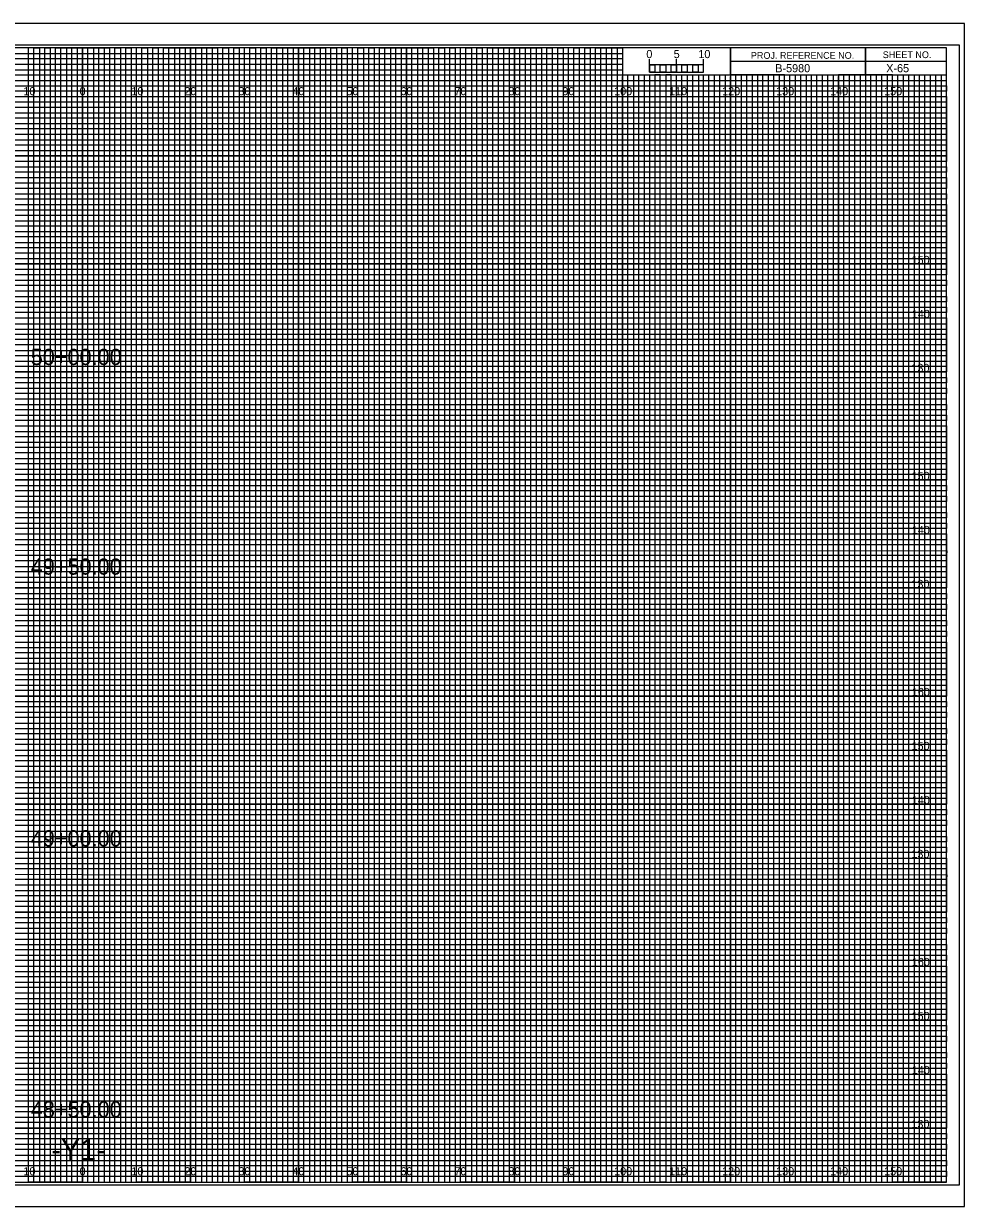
# Model space of a CAD drawing. Extents: x -13 to 323, y -5 to 4834.
# Drawn here: x 149.1 to 323.3, y 4175.5 to 4394.5 of the extents above; entities that cross this region are included whole.
import ezdxf

# ---------------------------------------------------------------- set-up
doc = ezdxf.new("R2010")
doc.units = 0
for name, color, linetype in [('Exist CMT Pavement', 7, 'Continuous'), ('Exist Cross Section Cell', 7, 'Continuous'), ('Exist XS Center Line Elevation Label', 7, 'Continuous'), ('Exist XS Ground Line', 7, 'Continuous'), ('Prop CMT Pvmt Course 1', 7, 'Continuous'), ('Prop CMT Pvmt Course 1 Wedge', 7, 'Continuous'), ('Prop CMT Pvmt Course 2', 7, 'Continuous'), ('Prop CMT Pvmt Course 2 Wedge', 7, 'Continuous'), ('Prop CMT Pvmt Course 3', 7, 'Continuous'), ('Prop CMT Pvmt Course 3 Wedge', 7, 'Continuous'), ('Prop CMT Pvmt Surface', 7, 'Continuous'), ('Prop CMT Pvmt Surface Shoulder', 7, 'Continuous'), ('Prop CMT Shld Paved Course 1', 7, 'Continuous'), ('Prop CMT Shld Paved Course 2', 7, 'Continuous'), ('Prop CMT Shld Paved Course 3', 7, 'Continuous'), ('Prop CMT Slope Grass', 7, 'Continuous'), ('Prop CMT Subgrade Earthwork', 7, 'Continuous')]:
    doc.layers.add(name, color=color, linetype=linetype)

msp = doc.modelspace()

# ---------------------------------------------------------------- linework, layer by layer
at = {"layer": 'Exist XS Center Line Elevation Label'}
for points in [[(145, 4180), (155, 4180), (155, 4390), (165, 4390), (165, 4180), (175, 4180), (175, 4390), (185, 4390), (185, 4180), (195, 4180), (195, 4390), (205, 4390), (205, 4180), (215, 4180), (215, 4390), (225, 4390), (225, 4180), (235, 4180), (235, 4390), (245, 4390), (245, 4180), (255, 4180), (255, 4390), (259.93, 4390), (260, 4390), (260, 4385), (264.99, 4385), (264.99, 4180), (275, 4180), (275, 4385), (285, 4385), (285, 4180), (295, 4180), (295, 4385), (305, 4385), (305, 4180), (315, 4180), (315, 4385)], [(0, 4385), (275, 4385)], [(0, 4365), (320, 4365), (320, 4375), (0, 4375)], [(0, 4345), (320, 4345), (320, 4355), (0, 4355)], [(0, 4325), (320, 4325), (320, 4335), (0, 4335)], [(0, 4305), (320, 4305), (320, 4315), (0, 4315)], [(0, 4285), (320, 4285), (320, 4295), (0, 4295)], [(0, 4265), (320, 4265), (320, 4275), (0, 4275)], [(0, 4245), (320, 4245), (320, 4255), (0, 4255)], [(0, 4225), (320, 4225), (320, 4235), (0, 4235)], [(0, 4205), (320, 4205), (320, 4215), (0, 4215)], [(0, 4185), (320, 4185), (320, 4195), (0, 4195)]]:
    msp.add_lwpolyline(points, dxfattribs=at)
at = {"layer": 'Exist XS Ground Line'}
for p, q in [((150, 4390), (140, 4390)), ((150, 4180), (150, 4390)), ((170, 4390), (160, 4390)), ((160, 4390), (160, 4180)), ((170, 4180), (170, 4390)), ((190, 4390), (180, 4390)), ((180, 4390), (180, 4180)), ((190, 4180), (190, 4390)), ((210, 4390), (200, 4390)), ((200, 4390), (200, 4180)), ((210, 4180), (210, 4390)), ((230, 4390), (220, 4390)), ((220, 4390), (220, 4180)), ((230, 4180), (230, 4390)), ((250, 4390), (240, 4390)), ((240, 4390), (240, 4180)), ((250, 4180), (250, 4390)), ((260, 4390), (260, 4180)), ((270, 4180), (270, 4385)), ((290, 4385), (280, 4385)), ((280, 4385), (280, 4180)), ((290, 4180), (290, 4385)), ((310, 4385), (300, 4385)), ((300, 4385), (300, 4180)), ((310, 4180), (310, 4385)), ((160, 4180), (150, 4180)), ((180, 4180), (170, 4180)), ((200, 4180), (190, 4180)), ((220, 4180), (210, 4180)), ((240, 4180), (230, 4180)), ((260, 4180), (250, 4180)), ((280, 4180), (270, 4180)), ((300, 4180), (290, 4180)), ((320, 4180), (310, 4180)), ((320, 4180), (320, 4180))]:
    msp.add_line(p, q, dxfattribs=at)
for points in [[(0, 4380), (320, 4380), (320, 4370), (0, 4370)], [(0, 4360), (320, 4360), (320, 4350), (0, 4350)], [(0, 4340), (320, 4340), (320, 4330), (0, 4330)], [(0, 4320), (320, 4320), (320, 4310), (0, 4310)], [(0, 4300), (320, 4300), (320, 4290), (0, 4290)], [(0, 4280), (320, 4280), (320, 4270), (0, 4270)], [(0, 4260), (320, 4260), (320, 4250), (0, 4250)], [(0, 4240), (320, 4240), (320, 4230), (0, 4230)], [(0, 4220), (320, 4220), (320, 4210), (0, 4210)], [(0, 4200), (320, 4200), (320, 4190), (0, 4190)]]:
    msp.add_lwpolyline(points, dxfattribs=at)
at = {"layer": 'Prop CMT Pvmt Course 1'}
for p, q in [((267, 4385), (266.01, 4385)), ((266.01, 4385), (266.01, 4180)), ((267, 4180), (267, 4385)), ((269, 4385), (268, 4385)), ((268, 4385), (268, 4180)), ((269, 4180), (269, 4385)), ((266.01, 4180), (265, 4180)), ((268, 4180), (267, 4180))]:
    msp.add_line(p, q, dxfattribs=at)
for points in [[(150, 4180), (151, 4180), (151, 4390), (152, 4390), (152, 4180)], [(152, 4180), (153, 4180), (153, 4390), (154, 4390), (154, 4180)], [(155, 4180), (156, 4180), (156, 4390), (157, 4390), (157, 4180)], [(157, 4180), (158, 4180), (158, 4390), (159, 4390), (159, 4180)], [(160, 4180), (161, 4180), (161, 4390), (162, 4390), (162, 4180)], [(162, 4180), (163, 4180), (163, 4390), (164, 4390), (164, 4180)], [(165, 4180), (166, 4180), (166, 4390), (167, 4390), (167, 4180)], [(167, 4180), (168, 4180), (168, 4390), (169, 4390), (169, 4180)], [(170, 4180), (171, 4180), (171, 4390), (172, 4390), (172, 4180)], [(172, 4180), (173, 4180), (173, 4390), (174, 4390), (174, 4180)], [(175, 4180), (176, 4180), (176, 4390), (177, 4390), (177, 4180)], [(177, 4180), (178, 4180), (178, 4390), (179, 4390), (179, 4180)], [(180, 4180), (181, 4180), (181, 4390), (182, 4390), (182, 4180)], [(182, 4180), (183, 4180), (183, 4390), (184, 4390), (184, 4180)], [(185, 4180), (186, 4180), (186, 4390), (187, 4390), (187, 4180)], [(187, 4180), (188, 4180), (188, 4390), (189, 4390), (189, 4180)], [(190, 4180), (191, 4180), (191, 4390), (192, 4390), (192, 4180)], [(192, 4180), (193, 4180), (193, 4390), (194, 4390), (194, 4180)], [(195, 4180), (196, 4180), (196, 4390), (197, 4390), (197, 4180)], [(197, 4180), (198, 4180), (198, 4390), (199, 4390), (199, 4180)], [(200, 4180), (201, 4180), (201, 4390), (202, 4390), (202, 4180)], [(202, 4180), (203, 4180), (203, 4390), (204, 4390), (204, 4180)], [(205, 4180), (206, 4180), (206, 4390), (207, 4390), (207, 4180)], [(207, 4180), (208, 4180), (208, 4390), (209, 4390), (209, 4180)], [(210, 4180), (211, 4180), (211, 4390), (212, 4390), (212, 4180)], [(212, 4180), (213, 4180), (213, 4390), (214, 4390), (214, 4180)], [(215, 4180), (216, 4180), (216, 4390), (217, 4390), (217, 4180)], [(217, 4180), (218, 4180), (218, 4390), (219, 4390), (219, 4180)], [(220, 4180), (221, 4180), (221, 4390), (222, 4390), (222, 4180)], [(222, 4180), (223, 4180), (223, 4390), (224, 4390), (224, 4180)], [(225, 4180), (226, 4180), (226, 4390), (227, 4390), (227, 4180)], [(227, 4180), (228, 4180), (228, 4390), (229, 4390), (229, 4180)], [(230, 4180), (231, 4180), (231, 4390), (232, 4390), (232, 4180)], [(232, 4180), (233, 4180), (233, 4390), (234, 4390), (234, 4180)], [(235, 4180), (236, 4180), (236, 4390), (237, 4390), (237, 4180)], [(237, 4180), (238, 4180), (238, 4390), (239, 4390), (239, 4180)], [(240, 4180), (241, 4180), (241, 4390), (242, 4390), (242, 4180)], [(242, 4180), (243, 4180), (243, 4390), (244, 4390), (244, 4180)], [(245, 4180), (246, 4180), (246, 4390), (247, 4390), (247, 4180)], [(247, 4180), (248, 4180), (248, 4390), (249, 4390), (249, 4180)], [(250, 4180), (251, 4180), (251, 4390), (252, 4390), (252, 4180)], [(252, 4180), (253, 4180), (253, 4390), (254, 4390), (254, 4180)], [(255, 4180), (256, 4180), (256, 4390), (257, 4390), (257, 4180)], [(257, 4180), (258, 4180), (258, 4390), (259, 4390), (259, 4180)], [(260, 4180), (261, 4180), (261, 4385), (262.02, 4385), (262.02, 4180)], [(262, 4180), (263, 4180), (263, 4385), (263.99, 4385), (263.99, 4180)], [(270, 4180), (270.98, 4180), (270.98, 4385), (272, 4385), (272, 4180)], [(272, 4180), (273, 4180), (273, 4385), (274.05, 4385), (274.05, 4180)], [(275, 4180), (276, 4180), (276, 4385), (277, 4385), (277, 4180)], [(277, 4180), (278, 4180), (278, 4385), (279, 4385), (279, 4180)], [(280, 4180), (281, 4180), (281, 4385), (282, 4385), (282, 4180)], [(282, 4180), (283, 4180), (283, 4385), (284, 4385), (284, 4180)], [(285, 4180), (286, 4180), (286, 4385), (287, 4385), (287, 4180)], [(287, 4180), (288, 4180), (288, 4385), (289, 4385), (289, 4180)], [(290, 4180), (291, 4180), (291, 4385), (292, 4385), (292, 4180)], [(292, 4180), (293, 4180), (293, 4385), (294, 4385), (294, 4180)], [(295, 4180), (296, 4180), (296, 4385), (297, 4385), (297, 4180)], [(297, 4180), (298, 4180), (298, 4385), (299, 4385), (299, 4180)], [(300, 4180), (301, 4180), (301, 4385), (302, 4385), (302, 4180)], [(302, 4180), (303, 4180), (303, 4385), (304, 4385), (304, 4180)], [(305, 4180), (306, 4180), (306, 4385), (307, 4385), (307, 4180)], [(307, 4180), (308, 4180), (308, 4385), (309, 4385), (309, 4180)], [(310, 4180), (311, 4180), (311, 4385), (312, 4385), (312, 4180)], [(312, 4180), (313, 4180), (313, 4385), (314, 4385), (314, 4180)], [(315, 4180), (316, 4180), (316, 4385), (317, 4385), (317, 4180)], [(317, 4180), (318, 4180), (318, 4385), (319, 4385), (319, 4180)]]:
    msp.add_lwpolyline(points, dxfattribs=at)
at = {"layer": 'Prop CMT Pvmt Course 2'}
for p, q in [((323.3, 4394.5), (-13.4, 4394.5)), ((-13.4, 4175.5), (323.3, 4175.5))]:
    msp.add_line(p, q, dxfattribs=at)
at = {"layer": 'Prop CMT Pvmt Surface Shoulder'}
for p, q in [((305, 4390), (305, 4385)), ((305, 4385), (305, 4390)), ((280, 4387.5), (280, 4385)), ((320, 4387.49), (280, 4387.49)), ((280, 4385), (320, 4385))]:
    msp.add_line(p, q, dxfattribs=at)
for points in [[(320, 4390), (0, 4390), (0, 4180), (320, 4180)], [(280, 4390), (260, 4390), (260, 4385.03), (280, 4385.03)], [(320, 4390), (280, 4390), (280, 4385), (320, 4385)]]:
    msp.add_lwpolyline(points, close=True, dxfattribs=at)
at = {"layer": 'Prop CMT Shld Paved Course 1'}
msp.add_lwpolyline([(-13.4, 4175.5), (323.3, 4175.5), (323.3, 4394.5), (-13.4, 4394.5)], close=True, dxfattribs=at)
at = {"layer": 'Prop CMT Shld Paved Course 2'}
msp.add_lwpolyline([(-10.8, 4179.5), (322.4, 4179.5), (322.4, 4390.5), (-10.8, 4390.5)], close=True, dxfattribs=at)
at = {"layer": 'Prop CMT Shld Paved Course 3'}
for p, q in [((150, 4180), (150, 4390)), ((160, 4180), (160, 4390)), ((170, 4180), (170, 4390)), ((180, 4180), (180, 4390)), ((190, 4180), (190, 4390)), ((200, 4180), (200, 4390)), ((210, 4180), (210, 4390)), ((220, 4180), (220, 4390)), ((230, 4180), (230, 4390)), ((240, 4180), (240, 4390)), ((250, 4180), (250, 4390)), ((260, 4180), (260, 4384.69)), ((270, 4180), (270, 4384.69)), ((280, 4180), (280, 4384.69)), ((290, 4180), (290, 4384.69)), ((300, 4180), (300, 4384.69)), ((310, 4180), (310, 4384.69)), ((0, 4380), (320, 4380)), ((0, 4370), (320, 4370)), ((0, 4360), (320, 4360)), ((0, 4350), (320, 4350)), ((0, 4340), (320, 4340)), ((0, 4330), (320, 4330)), ((0, 4320), (320, 4320)), ((0, 4310), (320, 4310)), ((0, 4300), (320, 4300)), ((0, 4290), (320, 4290)), ((0, 4280), (320, 4280)), ((0, 4270), (320, 4270)), ((0, 4260), (320, 4260)), ((0, 4250), (320, 4250)), ((0, 4240), (320, 4240)), ((0, 4230), (320, 4230)), ((0, 4220), (320, 4220)), ((0, 4210), (320, 4210)), ((0, 4200), (320, 4200)), ((0, 4190), (320, 4190))]:
    msp.add_line(p, q, dxfattribs=at)
at = {"layer": 'Prop CMT Slope Grass'}
for p, q in [((0, 4389), (260, 4389)), ((260, 4389), (260, 4387.98)), ((260, 4387.98), (0, 4387.98)), ((0, 4387), (260, 4387)), ((260, 4387), (260, 4385.89)), ((260, 4385.89), (0, 4385.89)), ((0, 4384), (320, 4384))]:
    msp.add_line(p, q, dxfattribs=at)
for points in [[(0, 4383), (270, 4383), (320, 4383), (320, 4382), (0, 4382)], [(0, 4381), (320, 4381), (320, 4379), (0, 4379)], [(0, 4378), (320, 4378), (320, 4377), (0, 4376.98)], [(0, 4376), (320, 4376), (320, 4374), (0, 4374)], [(0, 4373), (320, 4373), (320, 4372), (0, 4372)], [(0, 4371), (320, 4371), (320, 4369), (0, 4369)], [(0, 4368), (320, 4368), (320, 4367), (0, 4367)], [(0, 4366), (320, 4366), (320, 4364), (0, 4364)], [(0, 4363), (320, 4363), (320, 4362), (0, 4362)], [(0, 4361), (320, 4361), (320, 4359), (0, 4359)], [(0, 4358), (320, 4358), (320, 4357), (0, 4357)], [(0, 4356), (320, 4356), (320, 4353.95), (320, 4353), (320, 4352), (0, 4352)], [(0, 4354), (320, 4354), (320, 4353), (0, 4353)], [(0, 4351), (320, 4351), (320, 4349), (0, 4349.03)], [(0, 4349.03), (320, 4349), (320, 4348), (0, 4348)], [(0, 4347), (320, 4347), (320, 4346), (0, 4346)], [(0, 4344), (320, 4344), (320, 4343), (0, 4343)], [(0, 4342), (320, 4342), (320, 4341), (0, 4341)], [(-0.07, 4338.89), (320, 4338.89), (320, 4337.88), (-0.07, 4337.88)], [(0, 4337), (320, 4337), (320, 4336), (0, 4336)], [(0, 4334), (320, 4334), (320, 4333), (0, 4333)], [(0, 4332), (320, 4332), (320, 4331), (0, 4331)], [(0, 4329), (320, 4329), (320, 4328), (0, 4328)], [(0, 4327), (320, 4327), (320, 4326), (0, 4326)], [(0, 4324), (320, 4324), (320, 4323), (0, 4323)], [(0, 4322), (320, 4322), (320, 4321), (0, 4321)], [(0, 4319), (320, 4319), (319.99, 4317.98), (0, 4318)], [(0, 4317), (320, 4317), (320, 4316), (0, 4316)], [(0, 4314), (320, 4314), (320, 4313), (0, 4313)], [(0, 4312), (320, 4312), (320, 4311), (0, 4311)], [(0, 4309), (320, 4309), (320, 4308), (0, 4308)], [(0, 4307), (320, 4307), (320, 4306), (0, 4306)], [(0, 4304), (320, 4304), (320, 4303), (0, 4303)], [(0, 4302), (320, 4302), (320, 4301), (0, 4301)], [(0, 4299), (320, 4299), (320, 4298), (0, 4298)], [(0, 4296.99), (320.07, 4296.91), (320, 4296), (0, 4296)], [(0, 4294), (320, 4294), (320, 4293), (0, 4293)], [(0, 4292), (320, 4292), (320, 4291), (0, 4291)], [(0, 4289), (320, 4289), (320, 4288), (0, 4288)], [(0, 4287), (320, 4287), (320, 4286), (0, 4286)], [(0, 4284), (320, 4284), (320, 4283), (0, 4283)], [(0, 4282), (320, 4282), (320, 4281), (0, 4281)], [(0, 4279), (320, 4279), (320, 4278), (0, 4278)], [(0, 4277), (320, 4277), (320, 4276), (0, 4276)], [(0, 4274), (320, 4274), (320, 4273), (0, 4273)], [(0, 4272), (320, 4272), (320, 4271), (0, 4271)], [(0, 4269), (320, 4269), (320, 4268), (0, 4268)], [(0, 4267), (320, 4267), (320, 4266), (0, 4266)], [(0, 4264), (320, 4264), (320, 4263), (0, 4263)], [(0, 4262), (320, 4262), (320, 4261), (0, 4261)], [(0, 4259), (320, 4259), (319.99, 4257.98), (0, 4258)], [(0, 4257), (320, 4257), (320, 4256), (0, 4256)], [(0, 4254), (320, 4254), (320, 4253), (0, 4253)], [(0, 4252), (320, 4252), (320, 4251), (0, 4251)], [(0, 4249), (320, 4249), (320, 4248), (0, 4248)], [(0, 4247), (320, 4247), (320, 4246), (0, 4246)], [(0, 4244), (320, 4244), (320, 4243), (0, 4243)], [(0, 4242), (320, 4242), (320, 4241), (0, 4241)], [(0, 4239), (320, 4239), (320, 4238), (0, 4238)], [(0, 4236.99), (320.07, 4236.91), (320, 4236), (0, 4236)], [(0, 4234), (320, 4234), (320, 4233), (0, 4233)], [(0, 4232), (320, 4232), (320, 4231), (0, 4231)], [(0, 4229), (320, 4229), (320, 4228), (0, 4228)], [(0, 4227), (320, 4227), (320, 4226), (0, 4226)], [(0, 4224), (320, 4224), (320, 4223), (0, 4223)], [(0, 4222), (320, 4222), (320, 4221), (0, 4221)], [(0, 4219), (320, 4219), (320, 4218), (0, 4218)], [(0, 4217), (320, 4217), (320, 4216), (0, 4216)], [(0, 4214), (320, 4214), (320, 4213), (0, 4213)], [(0, 4212), (320, 4212), (320, 4211), (0, 4211)], [(0, 4209), (320, 4209), (320, 4208), (0, 4208)], [(0, 4207), (320, 4207), (320, 4206), (0, 4206)], [(0, 4204), (320, 4204), (320, 4203), (0, 4203)], [(0, 4202), (320, 4202), (320, 4201), (0, 4201)], [(0, 4199), (320, 4199), (320, 4198), (0, 4198)], [(0, 4197), (320, 4197), (320, 4196), (0, 4196)], [(0, 4194), (320, 4194), (320, 4193), (0, 4193)], [(0, 4192), (320, 4192), (320, 4191), (0, 4191)], [(0, 4189), (320, 4189), (320, 4188), (0, 4188)], [(0, 4187), (320, 4187), (320, 4186), (0, 4186)], [(0, 4184), (320, 4184), (320, 4183), (0, 4183)], [(0, 4182), (320, 4182), (320, 4181), (0, 4181)]]:
    msp.add_lwpolyline(points, dxfattribs=at)
at = {"layer": 'Prop CMT Subgrade Earthwork'}
for p, q in [((265, 4385.49), (265, 4387.9)), ((265, 4386.9), (265, 4387.9)), ((270, 4385.49), (270, 4387.9)), ((275, 4385.49), (275, 4387.9)), ((275, 4386.9), (275, 4387.9))]:
    msp.add_line(p, q, dxfattribs=at)
for points in [[(275, 4386.9), (265, 4386.9), (265, 4385.49), (275, 4385.49)], [(265, 4386.9), (266, 4386.9), (266, 4385.49), (265, 4385.49)], [(267, 4386.9), (268, 4386.9), (268, 4385.49), (267, 4385.49)], [(269, 4386.9), (270, 4386.9), (270, 4385.49), (269, 4385.49)], [(271, 4386.9), (272, 4386.9), (272, 4385.49), (271, 4385.49)], [(273, 4386.9), (274, 4386.9), (274, 4385.49), (273, 4385.49)]]:
    msp.add_lwpolyline(points, close=True, dxfattribs=at)

# ---------------------------------------------------------------- texts
at = {"layer": 'Exist CMT Pavement'}
msp.add_text('-Y1-', height=4, dxfattribs=at).set_placement((154.21, 4184))
at = {"layer": 'Exist Cross Section Cell'}
for s, p in [('10', (149.04, 4381.25)), ('0', (159.45, 4381.25)), ('0', (159.45, 4381.25)), ('10', (169.04, 4381.25)), ('20', (178.86, 4381.25)), ('30', (188.86, 4381.25)), ('40', (198.86, 4381.25)), ('50', (208.86, 4381.25)), ('60', (218.86, 4381.25)), ('70', (228.86, 4381.25)), ('80', (238.86, 4381.25)), ('90', (248.86, 4381.25)), ('100', (258.44, 4381.25)), ('110', (268.62, 4381.25)), ('120', (278.44, 4381.25)), ('130', (288.44, 4381.25)), ('140', (298.44, 4381.25)), ('150', (308.44, 4381.25)), ('10', (149.04, 4181.25)), ('0', (159.45, 4181.25)), ('0', (159.45, 4181.25)), ('10', (169.04, 4181.25)), ('20', (178.86, 4181.25)), ('30', (188.86, 4181.25)), ('40', (198.86, 4181.25)), ('50', (208.86, 4181.25)), ('60', (218.86, 4181.25)), ('70', (228.86, 4181.25)), ('80', (238.86, 4181.25)), ('90', (248.86, 4181.25)), ('100', (258.44, 4181.25)), ('110', (268.62, 4181.25)), ('120', (278.44, 4181.25)), ('130', (288.44, 4181.25)), ('140', (298.44, 4181.25)), ('150', (308.44, 4181.25))]:
    msp.add_text(s, height=1.5, dxfattribs=at).set_placement(p)
at = {"layer": 'Prop CMT Pvmt Course 1 Wedge'}
for s, p in [('50+00.00', (150.41, 4331.29)), ('49+50.00', (150.41, 4292.47)), ('49+00.00', (150.41, 4242.14)), ('48+50.00', (150.41, 4191.96))]:
    msp.add_text(s, height=3, dxfattribs=at).set_placement(p)
at = {"layer": 'Prop CMT Pvmt Course 2 Wedge'}
msp.add_text('X-65', height=1.5, dxfattribs=at).set_placement((308.83, 4385.5))
at = {"layer": 'Prop CMT Pvmt Course 3'}
for s, p in [('150', (313.52, 4350)), ('140', (313.57, 4340)), ('130', (313.49, 4330)), ('150', (313.52, 4310)), ('140', (313.57, 4300)), ('130', (313.49, 4290)), ('160', (313.57, 4270)), ('150', (313.52, 4260)), ('140', (313.57, 4250)), ('130', (313.49, 4240)), ('160', (313.57, 4220)), ('150', (313.52, 4210)), ('140', (313.57, 4200)), ('130', (313.49, 4190))]:
    msp.add_text(s, height=1.5, dxfattribs=at).set_placement(p)
at = {"layer": 'Prop CMT Pvmt Course 3 Wedge'}
msp.add_text('B-5980', height=1.5, dxfattribs=at).set_placement((288.28, 4385.5))
at = {"layer": 'Prop CMT Pvmt Surface'}
for s, p in [('5', (269.47, 4388.12)), ('10', (274.04, 4388.12))]:
    msp.add_text(s, height=1.5, dxfattribs=at).set_placement(p)
at = {"layer": 'Prop CMT Pvmt Surface Shoulder'}
for s, p in [('PROJ. REFERENCE NO.', (283.77, 4387.99)), ('SHEET NO.', (308.19, 4388.12))]:
    msp.add_text(s, height=1.25, dxfattribs=at).set_placement(p)
at = {"layer": 'Prop CMT Subgrade Earthwork'}
msp.add_text('0', height=1.5, dxfattribs=at).set_placement((264.41, 4388.12))

doc.saveas('drawing.dxf')
